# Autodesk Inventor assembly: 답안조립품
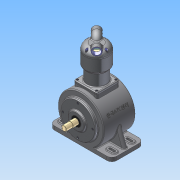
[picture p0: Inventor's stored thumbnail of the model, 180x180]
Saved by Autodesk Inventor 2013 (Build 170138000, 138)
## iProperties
Created: 2015-06
Part Number: 답안조립품
Document SubType Name: Assembly
Designer: ST4
Author: ST4
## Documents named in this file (15)
- C:\Users\ST4\Desktop\450605V1011\답안조립품.iam
- C:\Users\ST4\Desktop\450605V1011\본체.ipt
- C:\Users\ST4\Desktop\450605V1011\베어링 6204.ipt
- C:\Users\ST4\Desktop\450605V1011\크랭크 서브축.ipt
- C:\Users\ST4\Desktop\450605V1011\메인 크랭크 축-구동부.ipt
- C:\Users\ST4\Desktop\450605V1011\커넥팅 로드.ipt
- C:\Users\ST4\Desktop\450605V1011\베어링 NA 4902.ipt
- C:\Users\ST4\Desktop\450605V1011\메인커버.ipt
- C:\Users\ST4\Desktop\450605V1011\오일실.ipt
- C:\Users\ST4\Desktop\450605V1011\피스톤.ipt
- C:\Users\ST4\Desktop\450605V1011\피스톤 핀.ipt
- C:\Users\ST4\Desktop\450605V1011\실린더.ipt
- C:\Users\ST4\Desktop\450605V1011\실린더헤드.ipt
- C:\Users\ST4\Desktop\450605V1011\M5x0.8.ipt
- C:\Users\ST4\Desktop\450605V1011\M4x0.7.ipt
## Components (14 placed, 4 different names)
1. 피스톤:1
2. 피스톤 핀:1
3. M4x0.7:1
4. M4x0.7:2
5. M4x0.7:3
6. M4x0.7:4
7. M5x0.8:1
8. M5x0.8:2
9. M5x0.8:3
10. M5x0.8:4
11. M4x0.7:5
12. M4x0.7:6
13. M4x0.7:7
14. M4x0.7:8
